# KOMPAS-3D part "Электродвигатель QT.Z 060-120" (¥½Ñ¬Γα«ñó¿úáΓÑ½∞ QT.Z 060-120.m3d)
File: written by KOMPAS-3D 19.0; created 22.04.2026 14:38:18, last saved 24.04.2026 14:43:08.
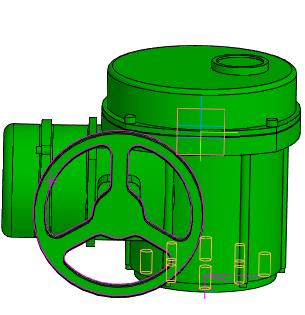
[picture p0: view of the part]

Document properties: Автор: Энергия; Полное имя файла: Z:\3.Личные\kachalov\3d для проектировщиков\1.7 Тип 023F.Z Затвор дисковый поворотный фланцевый с двумя эксцентриками\Привод\Электродвигатель QT.Z 060-120.m3d

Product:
- Part/product: Электродвигатель QT.Z 060-120
    Масса: 71.9422
  - Body: Тело 1
      Масса: 73.196

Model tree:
1. Эскиз:1
2. Элемент вращения:1
     Угол 1 = 360
3. Эскиз:2  (with: Элемент вращения:1)
4. Элемент выдавливания:1  (with: Элемент вращения:1)
     Расстояние 2 = 70
5. Эскиз:3  (with: Элемент вращения:1)
6. Элемент выдавливания:2
     Расстояние 1 = 147
7. Эскиз:4  (with: Элемент выдавливания:2)
8. Элемент выдавливания:3
     Расстояние 1 = 10
9. Эскиз:5  (with: Элемент выдавливания:2, Элемент выдавливания:3)
10. Элемент выдавливания:4  (with: Элемент вращения:1)
     Расстояние 1 = -147
11. Массив по концентрической сетке:1  (with: Элемент выдавливания:4, Эскиз:5, Элемент выдавливания:2)  (6 pattern instances)
     Шаг 2 = 360
12. Эскиз:6  (with: Элемент выдавливания:1)
13. Элемент выдавливания:5
     Расстояние 1 = 120
14. Эскиз:7  (with: Элемент выдавливания:5)
15. Элемент выдавливания:6
     Расстояние 1 = 10
16. Эскиз:9  (with: Элемент выдавливания:6)
17. Элемент вращения:3
     Угол 1 = 360
18. Эскиз:10  (with: Элемент выдавливания:1)
19. Элемент выдавливания:8
     Расстояние 1 = 110
20. Эскиз:11  (with: Элемент выдавливания:8)
21. Элемент выдавливания:9
     Расстояние 1 = 8
22. Эскиз:12  (with: Элемент выдавливания:9)
23. Элемент выдавливания:10
     Расстояние 1 = 40
24. Эскиз:19  (with: Элемент выдавливания:10)
25. Эскиз:20  (with: Элемент выдавливания:10)
26. Элемент выдавливания:14
     Расстояние 1 = 10
27. Эскиз:21  (with: Элемент выдавливания:14)
28. Элемент выдавливания:15
     Расстояние 1 = 40
29. Скругление:3  (with: Элемент выдавливания:15)
     Радиус = 10
30. Эскиз:22  (with: Элемент вращения:1)
31. Скругление:4  (with: Элемент выдавливания:10, Элемент выдавливания:14, Элемент выдавливания:15)
     Радиус = 2
32. Эскиз:23  (with: Элемент вращения:1)
33. Элемент выдавливания:16
     Расстояние 1 = 8
34. Эскиз:24  (with: Элемент выдавливания:16)
35. Элемент выдавливания:17
     Расстояние 2 = 2
36. Эскиз:25
37. Элемент выдавливания:19
     Расстояние 1 = 97
38. Эскиз:26  (with: Элемент выдавливания:19)
39. Элемент выдавливания:20
     Расстояние 1 = 35
40. Эскиз:27  (with: Элемент выдавливания:20)
41. Элемент выдавливания:21
     Расстояние 1 = 10
42. Эскиз:28  (with: Элемент выдавливания:21)
43. Элемент выдавливания:22
     Расстояние 1 = 10
44. Эскиз:29  (with: Элемент выдавливания:3)
45. Эскиз:30  (with: Элемент выдавливания:3)
46. Элемент выдавливания:23
     Расстояние 2 = 90
47. Эскиз:31  (with: Элемент выдавливания:3)
48. Элемент выдавливания:24
     Расстояние 2 = 2
49. Эскиз:32  (with: Элемент выдавливания:6)
50. Элемент выдавливания:25
     Расстояние 1 = 7
51. Эскиз:33  (with: Элемент вращения:1)
52. Элемент выдавливания:26
     Расстояние 1 = 7
53. Эскиз:34  (with: Элемент выдавливания:14)
54. Элемент выдавливания:27
     Расстояние 1 = 5
55. Скругление:6  (with: Элемент выдавливания:22)
     Радиус = 1
56. Эскиз:35  (with: Элемент выдавливания:2, Элемент выдавливания:4)
57. Элемент выдавливания:28
     Расстояние 1 = 5
58. Скругление:7  (with: Элемент вращения:1)
     Радиус = 5
59. Эскиз:36  (with: Элемент вращения:1)
60. Эскиз:37  (with: Элемент вращения:1)
61. Отверстие:3  (with: Элемент выдавливания:3)  (labels: M12)
     Глубина выреза = 30; Диаметр отверстия = 10.1056; Угол конуса дна = 118; Расстояние 1 = 57.5; Расстояние 2 = -8; Диаметр зенковки = 14; Глубина зенковки = 1.94722; Угол зенковки = 90
62. M12  (labels: M12; cil0_24705-2004 coarse)
     Длина резьбы = 25; Шаг резьбы = 1.75; Номинальный диаметр резьбы = 12
63. Отверстие:4  (with: Элемент выдавливания:3)  (labels: M10)
     Глубина выреза = 30; Диаметр отверстия = 8.3762; Угол конуса дна = 118; Расстояние 1 = 31.0624; Расстояние 2 = -44.0624; Диаметр зенковки = 12; Глубина зенковки = 1.8119; Угол зенковки = 90
64. M10  (labels: cil0_24705-2004 coarse)
     Длина резьбы = 25; Шаг резьбы = 1.5; Номинальный диаметр резьбы = 10
65. Массив по концентрической сетке:4  (with: Отверстие:3, Эскиз:29)  (labels: M12)  (2 pattern instances)
66. Отверстие:3  (with: Эскиз:29)  (labels: M12)
67. Отверстие:3  (with: Эскиз:29)  (labels: M12)
68. Массив по концентрической сетке:5  (with: Отверстие:4, Эскиз:29)  (labels: M10)  (2 pattern instances)
69. Отверстие:4  (with: Эскиз:29)  (labels: M10)
70. Отверстие:4  (with: Эскиз:29)  (labels: M10)
71. Эскиз:38  (with: Элемент вращения:1)

Expressions: 360/4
